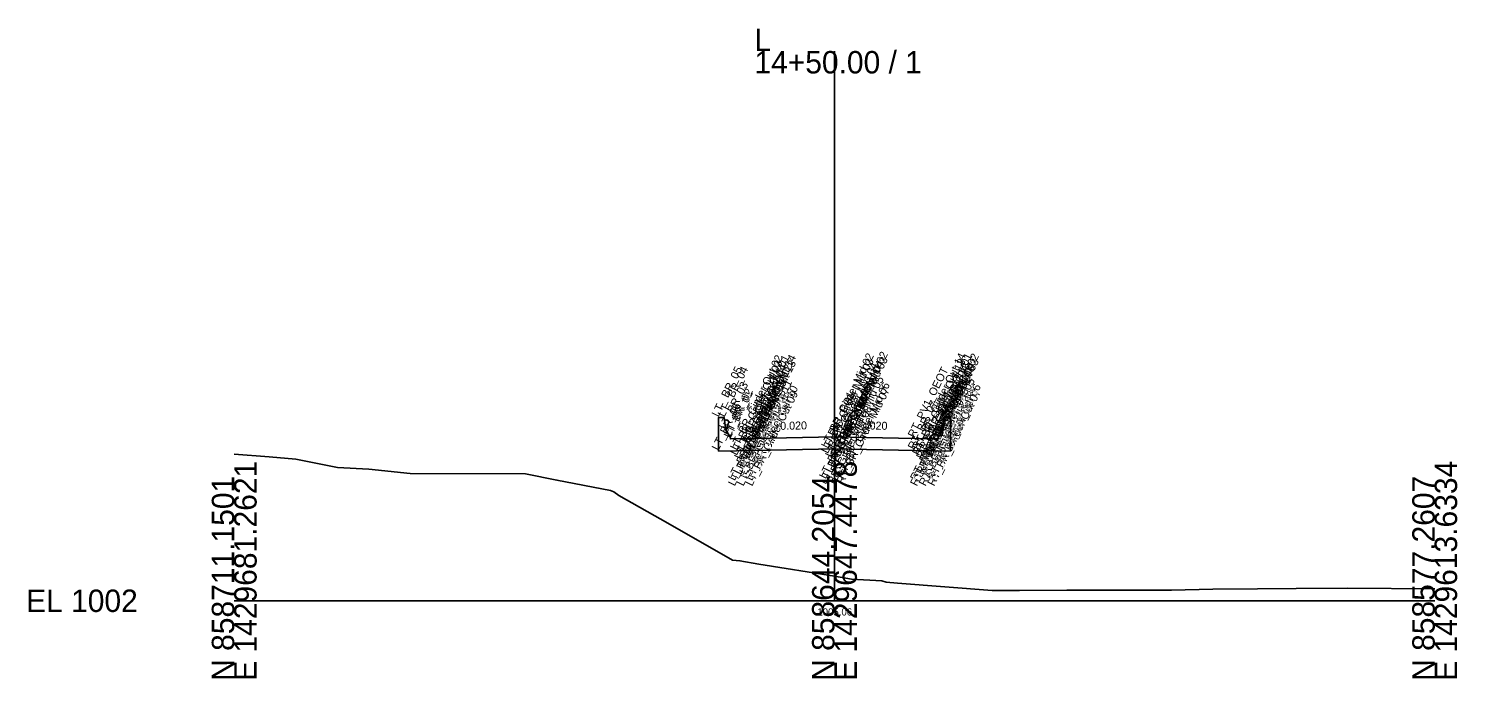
# Model space of a CAD drawing. Extents: x -26 to 153, y -10 to 13058.
# Drawn here: x -25.7 to 152.8, y 5990.3 to 6071.4 of the extents above; entities that cross this region are included whole.
import ezdxf

# ---------------------------------------------------------------- set-up
doc = ezdxf.new("R2010")
doc.units = 0
for name, color, linetype in [('Default', 7, 'Continuous'), ('Exist Cross Section Cell', 7, 'Continuous'), ('Exist XS Center Line Elevation Label', 7, 'Continuous'), ('Exist XS Ground Line', 7, 'Continuous'), ('Prop CMT Concrete Structures', 7, 'Continuous'), ('Prop XS Dump Level', 7, 'Continuous'), ('Prop XS SE Text', 7, 'Continuous')]:
    doc.layers.add(name, color=color, linetype=linetype)

msp = doc.modelspace()

# ---------------------------------------------------------------- linework, layer by layer
at = {"layer": 'Exist Cross Section Cell'}
for p, q in [((75, 6000), (75, 6068.65)), ((0, 6000), (75, 6000)), ((75, 6000), (150, 6000))]:
    msp.add_line(p, q, dxfattribs=at)
at = {"layer": 'Exist XS Ground Line'}
msp.add_lwpolyline([(0, 6018.29), (4.38, 6017.97), (7.68, 6017.7), (12.9, 6016.65), (16.81, 6016.43), (22, 6015.9), (36.38, 6015.84), (40.32, 6015.08), (47.01, 6013.78), (47.44, 6013.6), (48.07, 6013.16), (54.18, 6009.7), (62.26, 6005.07), (63.18, 6005), (65.54, 6004.59), (75, 6003.06), (77.15, 6002.71), (80.93, 6002.5), (81.45, 6002.31), (82.89, 6002.2), (94.71, 6001.27), (98.12, 6001.3), (104.03, 6001.31), (117.11, 6001.33), (122.27, 6001.45), (127.85, 6001.51), (132.7, 6001.52), (139.13, 6001.57), (150, 6001.48)], dxfattribs=at)
at = {"layer": 'Prop CMT Concrete Structures'}
for points in [[(75, 6020.48), (65, 6020.28), (62, 6020.22), (61.99, 6020.47), (61.41, 6021.3), (61.24, 6022.88), (60.5, 6022.88), (60.5, 6018.69)], [(75, 6020.48), (85, 6020.28), (88, 6020.22), (88.01, 6020.47), (88.59, 6021.3), (88.76, 6022.88), (89.5, 6022.88), (89.5, 6018.69)], [(75, 6018.98), (75, 6020.48)], [(75, 6018.98), (75, 6020.48)], [(60.5, 6018.69), (65, 6018.78), (75, 6018.98)], [(89.5, 6018.69), (85, 6018.78), (75, 6018.98)]]:
    msp.add_lwpolyline(points, dxfattribs=at)

# ---------------------------------------------------------------- texts
at = {"layer": 'Default'}
msp.add_text('-', height=0.0001, dxfattribs=at).set_placement((0, 6000))
at = {"layer": 'Exist Cross Section Cell'}
for s, p in [('L', (65, 6068.65)), ('14+50.00 / 1', (65, 6065.85)), ('EL 1002', (-26, 5998.6))]:
    msp.add_text(s, height=2.8, dxfattribs=at).set_placement(p)
for s, p in [('E 1429681.2621', (2.8, 5990)), ('E 1429647.4478', (77.8, 5990)), ('E 1429613.6334', (152.8, 5990)), ('N 858711.1501', (0, 5990)), ('N 858644.2054', (75, 5990)), ('N 858577.2607', (150, 5990))]:
    msp.add_text(s, height=2.8, rotation=90, dxfattribs=at).set_placement(p)
at = {"layer": 'Exist XS Center Line Elevation Label'}
msp.add_text('1005.06', height=0.9, dxfattribs=at).set_placement((72.86, 5998.16))
msp.add_text('1005.06', height=0.9, dxfattribs=at).set_placement((72.86, 5998.16))
msp.add_text('1005.06', height=0.9, dxfattribs=at).set_placement((72.86, 5998.16))
at = {"layer": 'Prop XS Dump Level'}
for s, p in [('LT_BR_Girder Mid 02', (74.17, 6018.96)), ('RT_BR_Girder Mid 02', (75.83, 6018.96)), ('RT_BR_Girder Out 14', (85.54, 6018.77)), ('RT_BR_Girder Out 02', (87.21, 6018.73)), ('LT_ BR_05', (60.5, 6022.88)), ('LT_ BR_04', (61.24, 6022.88)), ('LT_BR_Girder Out 02', (62.79, 6018.73)), ('LT_BR_Girder Out 03', (62.79, 6018.08)), ('LT_BR_Girder Out 04', (63.29, 6017.58)), ('LT_BR_Girder Out 01', (63.62, 6018.75)), ('LT_BR_Girder Out 12', (63.96, 6017.58)), ('LT_BR_Girder Out 14', (64.46, 6018.77)), ('LT_BR_Girder Out 13', (64.46, 6018.08)), ('LT_PV1_OEOT', (65, 6020.28)), ('LT_BR_Girder Mid 03', (74.17, 6018.31)), ('LT_BR_Girder Mid 04', (74.67, 6017.81)), ('RT_BR_Girder Mid 04', (75.33, 6017.81)), ('RT_BR_Girder Mid 03', (75.83, 6018.31)), ('RT_PV1_OEOT', (85, 6020.28)), ('RT_BR_Girder Out 13', (85.54, 6018.08)), ('RT_BR_Girder Out 12', (86.04, 6017.58)), ('RT_BR_Girder Out 01', (86.38, 6018.75)), ('RT_BR_Girder Out 04', (86.71, 6017.58)), ('RT_BR_Girder Out 03', (87.21, 6018.08)), ('RT_ BR_04', (88.76, 6022.88)), ('RT_ BR_05', (89.5, 6022.88)), ('LT_BR_03', (61.41, 6021.3)), ('LT_BR_Girder Out 05', (63.29, 6015.67)), ('LT_BR_Girder Out 11', (63.96, 6015.67)), ('LT_BR_Girder Mid 05', (74.67, 6015.89)), ('RT_BR_Girder Mid 05', (75.33, 6015.89)), ('RT_BR_Girder Mid 06', (76.08, 6015.14)), ('RT_BR_Girder Out 11', (86.04, 6015.67)), ('RT_BR_Girder Out 05', (86.71, 6015.67)), ('RT_BR_03', (88.59, 6021.3)), ('LT_BR_02', (61.99, 6020.47)), ('LT_BR_01', (62, 6020.22)), ('LT_BR_Girder Out 06', (62.54, 6014.92)), ('LT_BR_Girder Out 07', (62.54, 6014.25)), ('LT_BR_Girder Out 08', (63.62, 6014.25)), ('LT_BR_Girder Out 10', (64.71, 6014.92)), ('LT_BR_Girder Out 09', (64.71, 6014.25)), ('LT_BR_Girder Mid 06', (73.92, 6015.14)), ('LT_BR_Girder Mid 07', (73.92, 6014.48)), ('PV1_PGL', (75, 6020.48)), ('RT_BR_Girder Mid 07', (76.08, 6014.48)), ('RT_BR_Girder Out 10', (85.29, 6014.92)), ('RT_BR_Girder Out 09', (85.29, 6014.25)), ('RT_BR_Girder Out 08', (86.38, 6014.25)), ('RT_BR_Girder Out 06', (87.46, 6014.92)), ('RT_BR_Girder Out 07', (87.46, 6014.25)), ('RT_BR_01', (88, 6020.22)), ('RT_BR_02', (88.01, 6020.47)), ('LT_BR_06', (60.5, 6018.69)), ('LT_BR_07', (65, 6018.78)), ('BR_Girder Mid 08', (75, 6014.48)), ('BR_PGL', (75, 6018.98)), ('RT_BR_07', (85, 6018.78)), ('RT_BR_06', (89.5, 6018.69))]:
    msp.add_text(s, height=1, rotation=63.5833, dxfattribs=at).set_placement(p)
at = {"layer": 'Prop XS SE Text'}
for rotation, p in [(1.1458, (68.23, 6021.34)), (358.8542, (78.27, 6021.41))]:
    msp.add_text('0.020', height=1, rotation=rotation, dxfattribs=at).set_placement(p)

doc.saveas('drawing.dxf')
